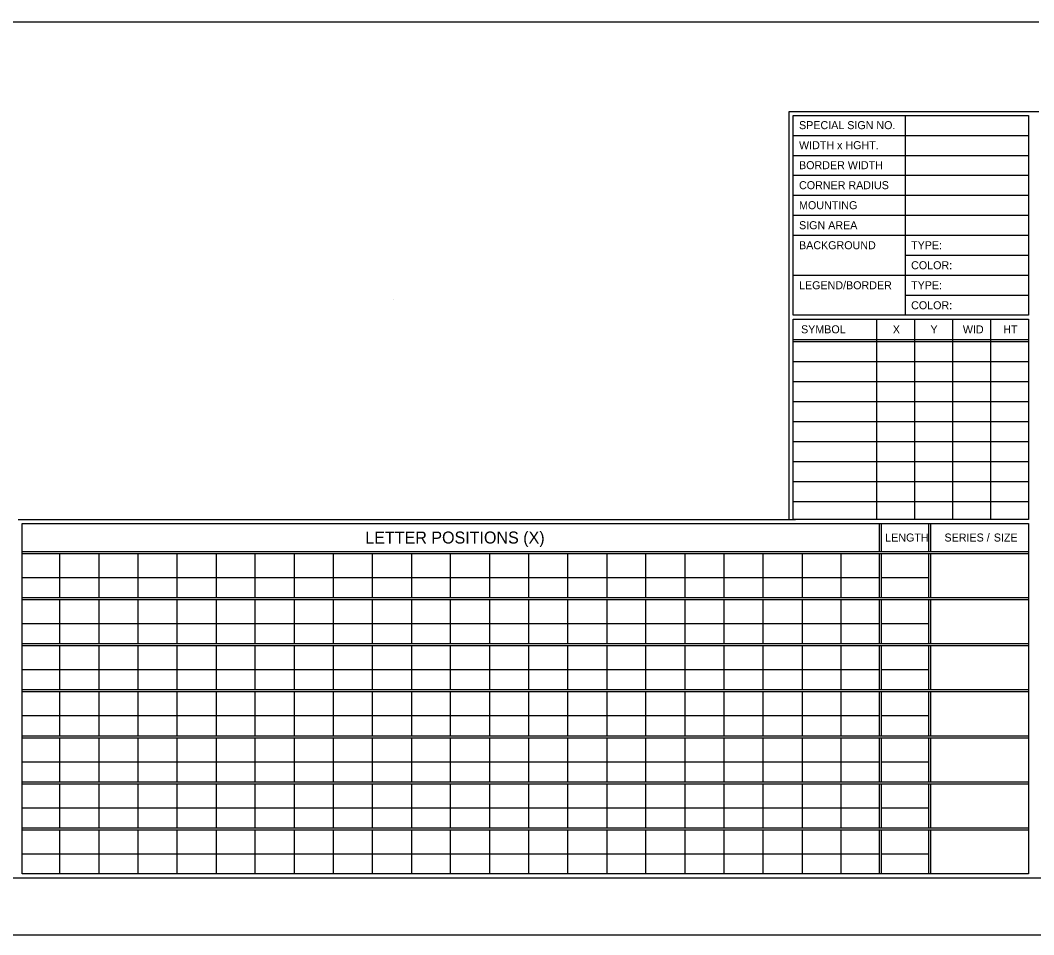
# Model space of a CAD drawing. Extents: x 2150010 to 2150174, y 145114 to 145224.
# Drawn here: x 2150076.4 to 2150135.1, y 145114.1 to 145167.1 of the extents above; entities that cross this region are included whole.
import ezdxf

# ---------------------------------------------------------------- set-up
doc = ezdxf.new("R2010")
doc.units = 0
for name, color, linetype in [('BORDER', 7, 'Continuous'), ('Level 1', 7, 'Continuous'), ('NON-PLOT', 7, 'Continuous'), ('PDF', 7, 'Continuous')]:
    doc.layers.add(name, color=color, linetype=linetype)

msp = doc.modelspace()

# ---------------------------------------------------------------- linework, layer by layer
at = {"layer": 'BORDER'}
for p, q in [((2150017.557, 145117.388), (2150171.536, 145117.388)), ((2150010.458, 145114.088), (2150174.061, 145114.088))]:
    msp.add_line(p, q, dxfattribs=at)
at = {"layer": 'Level 1'}
for p, q in [((2150135.447, 145166.95), (2150017.557, 145166.95)), ((2150120.969, 145161.778), (2150135.447, 145161.778)), ((2150127.694, 145161.546), (2150127.694, 145149.975)), ((2150121.201, 145160.387), (2150134.843, 145160.387)), ((2150121.201, 145159.227), (2150134.843, 145159.227)), ((2150121.201, 145158.091), (2150134.843, 145158.091)), ((2150121.201, 145156.932), (2150134.843, 145156.932)), ((2150121.201, 145155.772), (2150134.843, 145155.772)), ((2150121.201, 145154.613), (2150134.843, 145154.613)), ((2150127.694, 145153.453), (2150134.843, 145153.453)), ((2150121.201, 145152.294), (2150134.843, 145152.294)), ((2150127.694, 145151.134), (2150134.843, 145151.134)), ((2150121.201, 145138.143), (2150121.201, 145149.743)), ((2150121.201, 145149.743), (2150134.843, 145149.743)), ((2150126.031, 145149.737), (2150126.031, 145148.578)), ((2150128.234, 145149.737), (2150128.234, 145148.578)), ((2150130.437, 145149.737), (2150130.437, 145148.578)), ((2150132.64, 145149.737), (2150132.64, 145148.578)), ((2150134.843, 145149.743), (2150134.843, 145138.143)), ((2150121.201, 145148.578), (2150134.843, 145148.578)), ((2150121.201, 145148.462), (2150134.843, 145148.462)), ((2150126.031, 145148.578), (2150126.031, 145138.143)), ((2150128.234, 145148.578), (2150128.234, 145138.143)), ((2150130.437, 145148.578), (2150130.437, 145138.143)), ((2150132.64, 145148.578), (2150132.64, 145138.143)), ((2150121.201, 145147.303), (2150134.843, 145147.303)), ((2150121.201, 145146.143), (2150134.843, 145146.143)), ((2150121.201, 145144.984), (2150134.843, 145144.984)), ((2150121.201, 145143.824), (2150134.843, 145143.824)), ((2150121.201, 145142.665), (2150134.843, 145142.665)), ((2150121.201, 145141.505), (2150134.843, 145141.505)), ((2150121.201, 145140.346), (2150134.843, 145140.346)), ((2150121.201, 145139.186), (2150134.843, 145139.186)), ((2150076.316, 145138.143), (2150121.342, 145138.143)), ((2150134.843, 145138.143), (2150121.201, 145138.143)), ((2150126.185, 145137.911), (2150126.185, 145136.288)), ((2150126.301, 145137.911), (2150126.301, 145136.288)), ((2150129.048, 145137.911), (2150129.048, 145136.288)), ((2150129.164, 145137.911), (2150129.164, 145136.288)), ((2150076.548, 145136.288), (2150134.843, 145136.288)), ((2150076.548, 145136.172), (2150134.843, 145136.172)), ((2150078.704, 145136.172), (2150078.704, 145133.621)), ((2150080.977, 145136.172), (2150080.977, 145133.621)), ((2150083.25, 145136.172), (2150083.25, 145133.621)), ((2150085.499, 145136.172), (2150085.499, 145133.621)), ((2150087.772, 145136.172), (2150087.772, 145133.621)), ((2150090.021, 145136.172), (2150090.021, 145133.621)), ((2150092.294, 145136.172), (2150092.294, 145133.621)), ((2150094.566, 145136.172), (2150094.566, 145133.621)), ((2150096.816, 145136.172), (2150096.816, 145133.621)), ((2150099.088, 145136.172), (2150099.088, 145133.621)), ((2150101.337, 145136.172), (2150101.337, 145133.621)), ((2150103.61, 145136.172), (2150103.61, 145133.621)), ((2150105.883, 145136.172), (2150105.883, 145133.621)), ((2150108.132, 145136.172), (2150108.132, 145133.621)), ((2150110.405, 145136.172), (2150110.405, 145133.621)), ((2150112.654, 145136.172), (2150112.654, 145133.621)), ((2150114.927, 145136.172), (2150114.927, 145133.621)), ((2150117.199, 145136.172), (2150117.199, 145133.621)), ((2150119.449, 145136.172), (2150119.449, 145133.621)), ((2150121.721, 145136.172), (2150121.721, 145133.621)), ((2150123.97, 145136.172), (2150123.97, 145133.621)), ((2150126.185, 145136.172), (2150126.185, 145133.621)), ((2150126.301, 145136.172), (2150126.301, 145133.621)), ((2150129.048, 145136.172), (2150129.048, 145133.621)), ((2150129.164, 145136.172), (2150129.164, 145133.621)), ((2150076.548, 145134.78), (2150126.185, 145134.78)), ((2150126.301, 145134.78), (2150129.048, 145134.78)), ((2150076.548, 145133.621), (2150134.843, 145133.621)), ((2150076.548, 145133.505), (2150134.843, 145133.505)), ((2150078.704, 145133.505), (2150078.704, 145130.954)), ((2150080.977, 145133.505), (2150080.977, 145130.954)), ((2150083.25, 145133.505), (2150083.25, 145130.954)), ((2150085.499, 145133.505), (2150085.499, 145130.954)), ((2150087.772, 145133.505), (2150087.772, 145130.954)), ((2150090.021, 145133.505), (2150090.021, 145130.954)), ((2150092.294, 145133.505), (2150092.294, 145130.954)), ((2150094.566, 145133.505), (2150094.566, 145130.954)), ((2150096.816, 145133.505), (2150096.816, 145130.954)), ((2150099.088, 145133.505), (2150099.088, 145130.954)), ((2150101.337, 145133.505), (2150101.337, 145130.954)), ((2150103.61, 145133.505), (2150103.61, 145130.954)), ((2150105.883, 145133.505), (2150105.883, 145130.954)), ((2150108.132, 145133.505), (2150108.132, 145130.954)), ((2150110.405, 145133.505), (2150110.405, 145130.954)), ((2150112.654, 145133.505), (2150112.654, 145130.954)), ((2150114.927, 145133.505), (2150114.927, 145130.954)), ((2150117.199, 145133.505), (2150117.199, 145130.954)), ((2150119.449, 145133.505), (2150119.449, 145130.954)), ((2150121.721, 145133.505), (2150121.721, 145130.954)), ((2150123.97, 145133.505), (2150123.97, 145130.954)), ((2150126.185, 145133.505), (2150126.185, 145130.954)), ((2150126.301, 145133.505), (2150126.301, 145130.954)), ((2150129.048, 145133.505), (2150129.048, 145130.954)), ((2150129.164, 145133.505), (2150129.164, 145130.954)), ((2150076.548, 145132.113), (2150126.185, 145132.113)), ((2150126.301, 145132.113), (2150129.048, 145132.113)), ((2150076.548, 145130.954), (2150134.843, 145130.954)), ((2150076.548, 145130.838), (2150134.843, 145130.838)), ((2150078.704, 145130.838), (2150078.704, 145128.287)), ((2150080.977, 145130.838), (2150080.977, 145128.287)), ((2150083.25, 145130.838), (2150083.25, 145128.287)), ((2150085.499, 145130.838), (2150085.499, 145128.287)), ((2150087.772, 145130.838), (2150087.772, 145128.287)), ((2150090.021, 145130.838), (2150090.021, 145128.287)), ((2150092.294, 145130.838), (2150092.294, 145128.287)), ((2150094.566, 145130.838), (2150094.566, 145128.287)), ((2150096.816, 145130.838), (2150096.816, 145128.287)), ((2150099.088, 145130.838), (2150099.088, 145128.287)), ((2150101.337, 145130.838), (2150101.337, 145128.287)), ((2150103.61, 145130.838), (2150103.61, 145128.287)), ((2150105.883, 145130.838), (2150105.883, 145128.287)), ((2150108.132, 145130.838), (2150108.132, 145128.287)), ((2150110.405, 145130.838), (2150110.405, 145128.287)), ((2150112.654, 145130.838), (2150112.654, 145128.287)), ((2150114.927, 145130.838), (2150114.927, 145128.287)), ((2150117.199, 145130.838), (2150117.199, 145128.287)), ((2150119.449, 145130.838), (2150119.449, 145128.287)), ((2150121.721, 145130.838), (2150121.721, 145128.287)), ((2150123.97, 145130.838), (2150123.97, 145128.287)), ((2150126.185, 145130.838), (2150126.185, 145128.287)), ((2150126.301, 145130.838), (2150126.301, 145128.287)), ((2150129.048, 145130.838), (2150129.048, 145128.287)), ((2150129.164, 145130.838), (2150129.164, 145128.287)), ((2150076.548, 145129.447), (2150126.185, 145129.447)), ((2150126.301, 145129.447), (2150129.048, 145129.447)), ((2150076.548, 145128.287), (2150134.843, 145128.287)), ((2150076.548, 145128.171), (2150134.843, 145128.171)), ((2150078.704, 145128.171), (2150078.704, 145125.62)), ((2150080.977, 145128.171), (2150080.977, 145125.62)), ((2150083.25, 145128.171), (2150083.25, 145125.62)), ((2150085.499, 145128.171), (2150085.499, 145125.62)), ((2150087.772, 145128.171), (2150087.772, 145125.62)), ((2150090.021, 145128.171), (2150090.021, 145125.62)), ((2150092.294, 145128.171), (2150092.294, 145125.62)), ((2150094.566, 145128.171), (2150094.566, 145125.62)), ((2150096.816, 145128.171), (2150096.816, 145125.62)), ((2150099.088, 145128.171), (2150099.088, 145125.62)), ((2150101.337, 145128.171), (2150101.337, 145125.62)), ((2150103.61, 145128.171), (2150103.61, 145125.62)), ((2150105.883, 145128.171), (2150105.883, 145125.62)), ((2150108.132, 145128.171), (2150108.132, 145125.62)), ((2150110.405, 145128.171), (2150110.405, 145125.62)), ((2150112.654, 145128.171), (2150112.654, 145125.62)), ((2150114.927, 145128.171), (2150114.927, 145125.62)), ((2150117.199, 145128.171), (2150117.199, 145125.62)), ((2150119.449, 145128.171), (2150119.449, 145125.62)), ((2150121.721, 145128.171), (2150121.721, 145125.62)), ((2150123.97, 145128.171), (2150123.97, 145125.62)), ((2150126.185, 145128.171), (2150126.185, 145125.62)), ((2150126.301, 145128.171), (2150126.301, 145125.62)), ((2150129.048, 145128.171), (2150129.048, 145125.62)), ((2150129.164, 145128.171), (2150129.164, 145125.62)), ((2150076.548, 145126.78), (2150126.185, 145126.78)), ((2150126.301, 145126.78), (2150129.048, 145126.78)), ((2150076.548, 145125.62), (2150134.843, 145125.62)), ((2150076.548, 145125.504), (2150134.843, 145125.504)), ((2150078.704, 145125.504), (2150078.704, 145122.954)), ((2150080.977, 145125.504), (2150080.977, 145122.954)), ((2150083.25, 145125.504), (2150083.25, 145122.954)), ((2150085.499, 145125.504), (2150085.499, 145122.954)), ((2150087.772, 145125.504), (2150087.772, 145122.954)), ((2150090.021, 145125.504), (2150090.021, 145122.954)), ((2150092.294, 145125.504), (2150092.294, 145122.954)), ((2150094.566, 145125.504), (2150094.566, 145122.954)), ((2150096.816, 145125.504), (2150096.816, 145122.954)), ((2150099.088, 145125.504), (2150099.088, 145122.954)), ((2150101.337, 145125.504), (2150101.337, 145122.954)), ((2150103.61, 145125.504), (2150103.61, 145122.954)), ((2150105.883, 145125.504), (2150105.883, 145122.954)), ((2150108.132, 145125.504), (2150108.132, 145122.954)), ((2150110.405, 145125.504), (2150110.405, 145122.954)), ((2150112.654, 145125.504), (2150112.654, 145122.954)), ((2150114.927, 145125.504), (2150114.927, 145122.954)), ((2150117.199, 145125.504), (2150117.199, 145122.954)), ((2150119.449, 145125.504), (2150119.449, 145122.954)), ((2150121.721, 145125.504), (2150121.721, 145122.954)), ((2150123.97, 145125.504), (2150123.97, 145122.954)), ((2150126.185, 145125.504), (2150126.185, 145122.954)), ((2150126.301, 145125.504), (2150126.301, 145122.954)), ((2150129.048, 145125.504), (2150129.048, 145122.954)), ((2150129.164, 145125.504), (2150129.164, 145122.954)), ((2150076.548, 145124.113), (2150126.185, 145124.113)), ((2150126.301, 145124.113), (2150129.048, 145124.113)), ((2150076.548, 145122.954), (2150134.843, 145122.954)), ((2150076.548, 145122.838), (2150134.843, 145122.838)), ((2150078.704, 145122.838), (2150078.704, 145120.287)), ((2150080.977, 145122.838), (2150080.977, 145120.287)), ((2150083.25, 145122.838), (2150083.25, 145120.287)), ((2150085.499, 145122.838), (2150085.499, 145120.287)), ((2150087.772, 145122.838), (2150087.772, 145120.287)), ((2150090.021, 145122.838), (2150090.021, 145120.287)), ((2150092.294, 145122.838), (2150092.294, 145120.287)), ((2150094.566, 145122.838), (2150094.566, 145120.287)), ((2150096.816, 145122.838), (2150096.816, 145120.287)), ((2150099.088, 145122.838), (2150099.088, 145120.287)), ((2150101.337, 145122.838), (2150101.337, 145120.287)), ((2150103.61, 145122.838), (2150103.61, 145120.287)), ((2150105.883, 145122.838), (2150105.883, 145120.287)), ((2150108.132, 145122.838), (2150108.132, 145120.287)), ((2150110.405, 145122.838), (2150110.405, 145120.287)), ((2150112.654, 145122.838), (2150112.654, 145120.287)), ((2150114.927, 145122.838), (2150114.927, 145120.287)), ((2150117.199, 145122.838), (2150117.199, 145120.287)), ((2150119.449, 145122.838), (2150119.449, 145120.287)), ((2150121.721, 145122.838), (2150121.721, 145120.287)), ((2150123.97, 145122.838), (2150123.97, 145120.287)), ((2150126.185, 145122.838), (2150126.185, 145120.287)), ((2150126.301, 145122.838), (2150126.301, 145120.287)), ((2150129.048, 145122.838), (2150129.048, 145120.287)), ((2150129.164, 145122.838), (2150129.164, 145120.287)), ((2150076.548, 145121.446), (2150126.185, 145121.446)), ((2150126.301, 145121.446), (2150129.048, 145121.446)), ((2150076.548, 145120.287), (2150134.843, 145120.287)), ((2150076.548, 145120.171), (2150134.843, 145120.171)), ((2150078.704, 145120.171), (2150078.704, 145117.62)), ((2150080.977, 145120.171), (2150080.977, 145117.62)), ((2150083.25, 145120.171), (2150083.25, 145117.62)), ((2150085.499, 145120.171), (2150085.499, 145117.62)), ((2150087.772, 145120.171), (2150087.772, 145117.62)), ((2150090.021, 145120.171), (2150090.021, 145117.62)), ((2150092.294, 145120.171), (2150092.294, 145117.62)), ((2150094.566, 145120.171), (2150094.566, 145117.62)), ((2150096.816, 145120.171), (2150096.816, 145117.62)), ((2150099.088, 145120.171), (2150099.088, 145117.62)), ((2150101.337, 145120.171), (2150101.337, 145117.62)), ((2150103.61, 145120.171), (2150103.61, 145117.62)), ((2150105.883, 145120.171), (2150105.883, 145117.62)), ((2150108.132, 145120.171), (2150108.132, 145117.62)), ((2150110.405, 145120.171), (2150110.405, 145117.62)), ((2150112.654, 145120.171), (2150112.654, 145117.62)), ((2150114.927, 145120.171), (2150114.927, 145117.62)), ((2150117.199, 145120.171), (2150117.199, 145117.62)), ((2150119.449, 145120.171), (2150119.449, 145117.62)), ((2150121.721, 145120.171), (2150121.721, 145117.62)), ((2150123.97, 145120.171), (2150123.97, 145117.62)), ((2150126.185, 145120.171), (2150126.185, 145117.62)), ((2150126.301, 145120.171), (2150126.301, 145117.62)), ((2150129.048, 145120.171), (2150129.048, 145117.62)), ((2150129.164, 145120.171), (2150129.164, 145117.62)), ((2150076.548, 145118.779), (2150126.185, 145118.779)), ((2150126.301, 145118.779), (2150129.048, 145118.779))]:
    msp.add_line(p, q, dxfattribs=at)
msp.add_lwpolyline([(2150120.969, 145138.143), (2150120.969, 145161.778)], dxfattribs=at)
for points in [[(2150121.201, 145161.546), (2150134.843, 145161.546), (2150134.843, 145149.975), (2150121.201, 145149.975)], [(2150076.548, 145137.911), (2150134.843, 145137.911), (2150134.843, 145117.62), (2150076.548, 145117.62)]]:
    msp.add_lwpolyline(points, close=True, dxfattribs=at)
at = {"layer": 'NON-PLOT'}
msp.add_line((2150098.029, 145150.883), (2150098.029, 145150.883), dxfattribs=at)
at = {"layer": 'PDF'}
msp.add_lwpolyline([(2150010.458, 145114.088), (2150174.061, 145114.088), (2150174.061, 145219.948), (2150010.458, 145219.948)], close=True, dxfattribs=at)

# ---------------------------------------------------------------- texts
at = {"layer": 'Level 1'}
for s, height, p in [('SPECIAL SIGN NO.', 0.46374, (2150121.549, 145160.758)), ('WIDTH x HGHT.', 0.46374, (2150121.549, 145159.598)), ('BORDER WIDTH', 0.46374, (2150121.549, 145158.439)), ('CORNER RADIUS', 0.46374, (2150121.549, 145157.28)), ('MOUNTING', 0.4637, (2150121.549, 145156.12)), ('SIGN AREA', 0.4638, (2150121.549, 145154.961)), ('BACKGROUND', 0.4637, (2150121.549, 145153.801)), ('TYPE:', 0.4637, (2150128.042, 145153.801)), ('COLOR:', 0.4637, (2150128.042, 145152.642)), ('LEGEND/BORDER', 0.46374, (2150121.549, 145151.482)), ('TYPE:', 0.4637, (2150128.042, 145151.482)), ('COLOR:', 0.4637, (2150128.042, 145150.323)), ('SYMBOL', 0.4637, (2150121.665, 145148.931)), ('X', 0.464, (2150126.981, 145148.926)), ('Y', 0.464, (2150129.161, 145148.926)), ('WID', 0.4637, (2150131.04, 145148.926)), ('HT', 0.4637, (2150133.382, 145148.926)), ('LETTER POSITIONS (X)', 0.69555, (2150096.422, 145136.751)), ('LENGTH', 0.4638, (2150126.541, 145136.867)), ('LENGTH', 0.4638, (2150126.541, 145136.867)), ('SERIES /', 0.4638, (2150129.975, 145136.867)), ('SIZE', 0.4638, (2150132.832, 145136.867))]:
    msp.add_text(s, height=height, dxfattribs=at).set_placement(p)

doc.saveas('drawing.dxf')
